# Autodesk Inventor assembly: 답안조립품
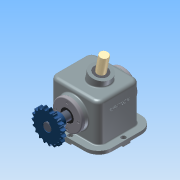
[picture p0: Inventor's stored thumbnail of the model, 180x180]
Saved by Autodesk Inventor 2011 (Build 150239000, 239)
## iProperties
Company: 한국ATC센터
Created: 2014-07
Part Number: 답안조립품
Document SubType Name: Assembly
Designer: KYOUNG IL JANG
Mass: 6548.08 g
Surface Area: 3444.33 cm^2
Volume: 1649.71 cm^3
Density: 3.96923 g/cm^3
Author: KYOUNG IL JANG
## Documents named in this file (13)
- C:\Users\SDA16\Desktop\441122V1010\답안조립품.iam
- C:\Users\SDA16\Desktop\441122V1010\뒤커버.ipt
- C:\Users\SDA16\Desktop\441122V1010\앞커버.ipt
- C:\Users\SDA16\Desktop\441122V1010\베어링 6205.ipt
- C:\Users\SDA16\Desktop\441122V1010\편심축.ipt
- C:\Users\SDA16\Desktop\441122V1010\슬라이드.ipt
- C:\Users\SDA16\Desktop\441122V1010\부시.ipt
- C:\Users\SDA16\Desktop\441122V1010\오일실.ipt
- C:\Users\SDA16\Desktop\441122V1010\키 8x8.ipt
- C:\Users\SDA16\Desktop\441122V1010\M4x0.5.ipt
- C:\Users\SDA16\Desktop\441122V1010\5-체인 스프로킷.ipt
- C:\Users\SDA16\Desktop\441122V1010\멈춤나사 M5x0.5.ipt
- C:\Users\SDA16\Desktop\441122V1010\1.본체.ipt
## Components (10 placed, 3 different names)
1. 1.본체:1
2. 5-체인 스프로킷:1 — 각도:2
3. M4x0.5:1
4. M4x0.5:2
5. M4x0.5:3
6. M4x0.5:7
7. M4x0.5:4
8. M4x0.5:5
9. M4x0.5:6
10. M4x0.5:8
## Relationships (1: Angle 1)
- 각도:2 [Angle]: 5-체인 스프로킷:1
